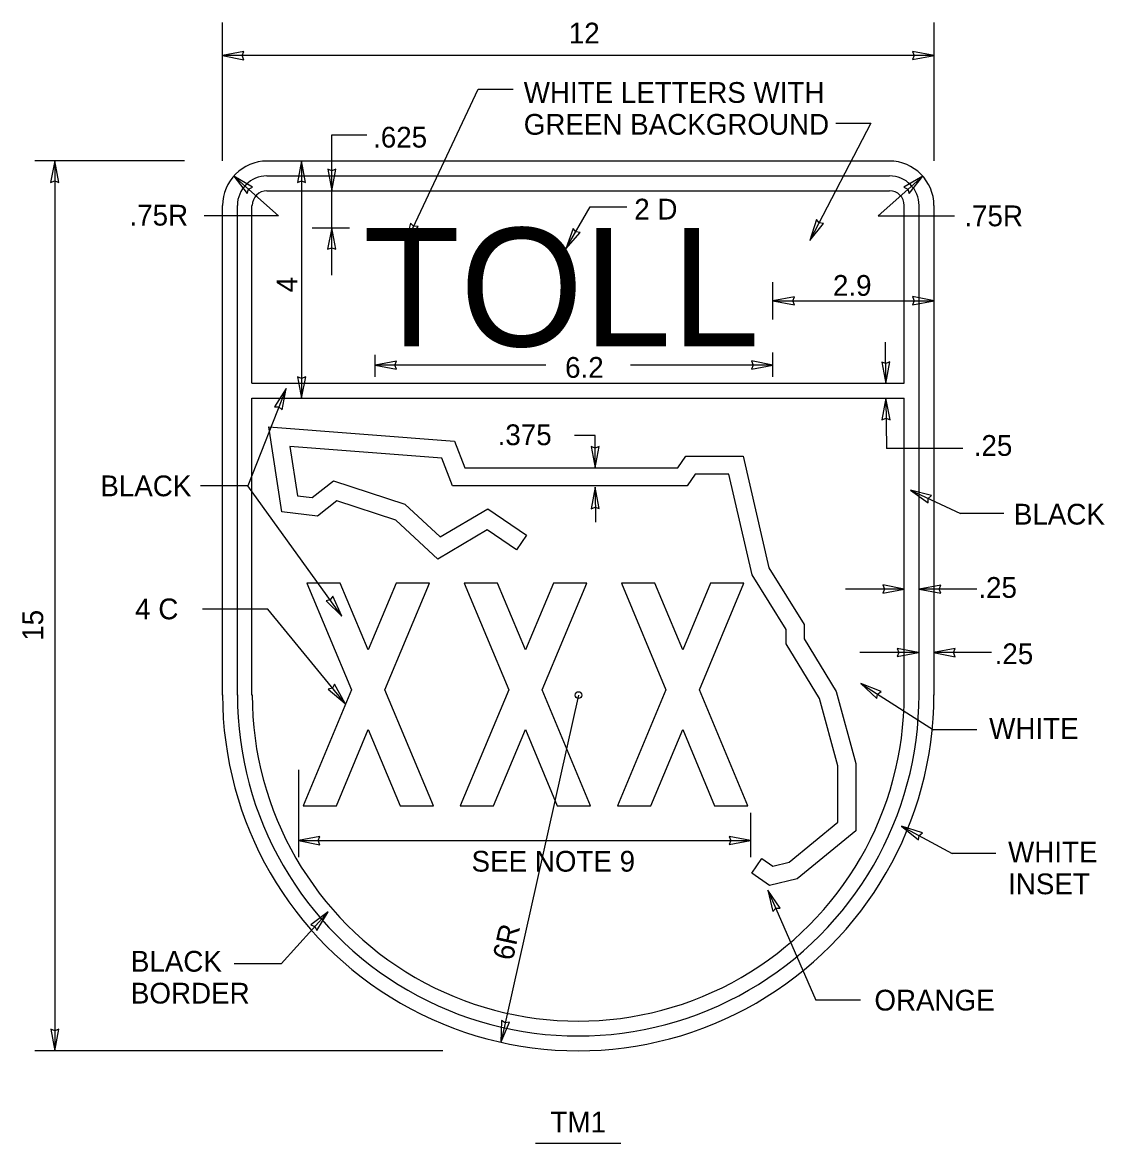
# Model space of a CAD drawing. Extents: x 56108 to 56738, y 11696 to 12112.
# Drawn here: x 56363.6 to 56509.5, y 11960.4 to 12111.6 of the extents above; entities that cross this region are included whole.
import ezdxf

# ---------------------------------------------------------------- set-up
doc = ezdxf.new("R2010")
doc.units = 0
for name, color, linetype in [('GSDims', 7, 'Continuous'), ('SignDetail', 7, 'Continuous'), ('SignPanel', 7, 'Continuous')]:
    doc.layers.add(name, color=color, linetype=linetype)

msp = doc.modelspace()

# ---------------------------------------------------------------- linework, layer by layer
at = {"layer": 'GSDims'}
for p, q in [((56390.53, 12092.88), (56390.53, 12111.55)), ((56486.53, 12092.88), (56486.53, 12111.55)), ((56393.43, 12107.63), (56390.53, 12107.09)), ((56393.21, 12107.09), (56393.43, 12107.63)), ((56486.53, 12107.09), (56483.63, 12107.65)), ((56483.63, 12107.65), (56483.85, 12107.09)), ((56486.53, 12107.09), (56390.53, 12107.09)), ((56390.53, 12107.09), (56393.43, 12106.53)), ((56393.43, 12106.53), (56393.21, 12107.09)), ((56483.85, 12107.09), (56483.63, 12106.55)), ((56483.63, 12106.55), (56486.53, 12107.09)), ((56415.18, 12081.63), (56425.03, 12102.57)), ((56425.03, 12102.57), (56429.76, 12102.57)), ((56478, 12097.95), (56469.79, 12082.15)), ((56473.28, 12097.95), (56478, 12097.95)), ((56405.28, 12088.85), (56405.28, 12096.41)), ((56405.28, 12096.41), (56410.01, 12096.41)), ((56385.42, 12092.88), (56365.24, 12092.88)), ((56367.92, 12092.88), (56367.36, 12089.98)), ((56367.92, 12092.88), (56367.92, 11972.88)), ((56368.46, 12089.98), (56367.92, 12092.88)), ((56401.22, 12092.88), (56400.66, 12089.98)), ((56401.22, 12092.88), (56401.22, 12060.87)), ((56401.76, 12089.98), (56401.22, 12092.88)), ((56486.53, 12092.88), (56486.53, 12092.88)), ((56392.07, 12090.84), (56398.09, 12085.49)), ((56392.07, 12090.84), (56393.86, 12088.5)), ((56394.59, 12089.32), (56392.07, 12090.84)), ((56405.28, 12091.53), (56404.74, 12091.75)), ((56404.74, 12091.75), (56405.28, 12088.85)), ((56405.28, 12088.85), (56405.84, 12091.75)), ((56405.84, 12091.75), (56405.28, 12091.53)), ((56485, 12090.84), (56478.98, 12085.49)), ((56485, 12090.84), (56482.46, 12089.34)), ((56483.19, 12088.51), (56485, 12090.84)), ((56367.36, 12089.98), (56367.92, 12090.2)), ((56367.92, 12090.2), (56368.46, 12089.98)), ((56394.07, 12089.06), (56394.59, 12089.32)), ((56400.66, 12089.98), (56401.22, 12090.2)), ((56401.22, 12090.2), (56401.76, 12089.98)), ((56482.46, 12089.34), (56482.99, 12089.06)), ((56393.86, 12088.5), (56394.07, 12089.06)), ((56405.28, 12083.86), (56405.28, 12088.85)), ((56482.99, 12089.06), (56483.19, 12088.51)), ((56436.85, 12081.01), (56440.14, 12086.67)), ((56440.14, 12086.67), (56445.08, 12086.67)), ((56398.09, 12085.49), (56388.08, 12085.49)), ((56470.65, 12084.97), (56469.79, 12082.15)), ((56471.02, 12084.52), (56470.65, 12084.97)), ((56478.98, 12085.49), (56489.29, 12085.49)), ((56402.65, 12083.86), (56407.66, 12083.86)), ((56405.28, 12083.86), (56404.72, 12080.96)), ((56405.28, 12077.48), (56405.28, 12083.86)), ((56405.82, 12080.96), (56405.28, 12083.86)), ((56415.92, 12084.49), (56415.18, 12081.63)), ((56415.18, 12081.63), (56416.92, 12084.02)), ((56416.32, 12084.06), (56415.92, 12084.49)), ((56416.92, 12084.02), (56416.32, 12084.06)), ((56437.84, 12083.78), (56436.85, 12081.01)), ((56436.85, 12081.01), (56438.79, 12083.23)), ((56438.2, 12083.32), (56437.84, 12083.78)), ((56438.79, 12083.23), (56438.2, 12083.32)), ((56469.79, 12082.15), (56471.62, 12084.46)), ((56471.62, 12084.46), (56471.02, 12084.52)), ((56404.72, 12080.96), (56405.28, 12081.18)), ((56405.28, 12081.18), (56405.82, 12080.96)), ((56464.8, 12071.5), (56464.8, 12076.52)), ((56467.7, 12074.56), (56464.8, 12074.02)), ((56467.48, 12074.02), (56467.7, 12074.56)), ((56486.53, 12074.02), (56483.63, 12074.58)), ((56483.63, 12074.58), (56483.85, 12074.02)), ((56464.8, 12074.02), (56486.53, 12074.02)), ((56464.8, 12074.02), (56467.7, 12073.46)), ((56467.7, 12073.46), (56467.48, 12074.02)), ((56483.85, 12074.02), (56483.63, 12073.48)), ((56483.63, 12073.48), (56486.53, 12074.02)), ((56480.03, 12062.87), (56479.98, 12068.46)), ((56411.12, 12063.75), (56411.12, 12066.73)), ((56464.8, 12063.75), (56464.8, 12067.06)), ((56414.02, 12065.88), (56411.12, 12065.34)), ((56434.17, 12065.34), (56411.12, 12065.34)), ((56411.12, 12065.34), (56414.02, 12064.78)), ((56413.8, 12065.34), (56414.02, 12065.88)), ((56414.02, 12064.78), (56413.8, 12065.34)), ((56464.8, 12065.34), (56445.56, 12065.34)), ((56464.8, 12065.34), (56461.9, 12065.9)), ((56461.9, 12065.9), (56462.12, 12065.34)), ((56462.12, 12065.34), (56461.9, 12064.8)), ((56461.9, 12064.8), (56464.8, 12065.34)), ((56480.01, 12065.55), (56479.47, 12065.76)), ((56479.47, 12065.76), (56480.03, 12062.87)), ((56480.57, 12065.77), (56480.01, 12065.55)), ((56480.03, 12062.87), (56480.57, 12065.77)), ((56401.22, 12063.55), (56400.68, 12063.77)), ((56400.68, 12063.77), (56401.22, 12060.87)), ((56401.22, 12060.87), (56401.78, 12063.77)), ((56401.78, 12063.77), (56401.22, 12063.55)), ((56399.14, 12062.2), (56393.98, 12049.06)), ((56399.14, 12062.2), (56397.56, 12059.7)), ((56398.58, 12059.3), (56399.14, 12062.2)), ((56480.03, 12060.87), (56479.5, 12057.97)), ((56480.03, 12060.87), (56480.1, 12054.11)), ((56480.6, 12057.98), (56480.03, 12060.87)), ((56397.56, 12059.7), (56398.16, 12059.7)), ((56398.16, 12059.7), (56398.58, 12059.3)), ((56479.5, 12057.97), (56480.06, 12058.19)), ((56480.06, 12058.19), (56480.6, 12057.98)), ((56440.8, 12055.87), (56438.04, 12055.87)), ((56440.8, 12054.16), (56440.26, 12054.38)), ((56440.26, 12054.38), (56440.8, 12051.48)), ((56440.8, 12051.48), (56440.8, 12055.87)), ((56440.8, 12051.48), (56441.36, 12054.38)), ((56441.36, 12054.38), (56440.8, 12054.16)), ((56410.03, 12053.44), (56410.03, 12053.44)), ((56490.39, 12054.11), (56480.1, 12054.11)), ((56393.98, 12049.06), (56387.6, 12049.06)), ((56406.65, 12031.51), (56393.98, 12049.06)), ((56440.8, 12048.88), (56440.27, 12045.98)), ((56440.8, 12048.88), (56440.86, 12044.17)), ((56441.37, 12045.99), (56440.8, 12048.88)), ((56483.33, 12048.5), (56490.09, 12045.34)), ((56483.33, 12048.5), (56485.72, 12046.76)), ((56486.18, 12047.76), (56483.33, 12048.5)), ((56485.72, 12046.76), (56485.75, 12047.36)), ((56485.75, 12047.36), (56486.18, 12047.76)), ((56440.27, 12045.98), (56440.83, 12046.2)), ((56440.83, 12046.2), (56441.37, 12045.99)), ((56495.94, 12045.34), (56490.09, 12045.34)), ((56482.5, 12035.15), (56474.59, 12035.15)), ((56482.5, 12035.15), (56479.6, 12035.71)), ((56479.6, 12035.71), (56479.82, 12035.15)), ((56479.82, 12035.15), (56479.6, 12034.61)), ((56479.6, 12034.61), (56482.5, 12035.15)), ((56487.42, 12035.69), (56484.52, 12035.15)), ((56492.31, 12035.15), (56484.52, 12035.15)), ((56484.52, 12035.15), (56487.42, 12034.59)), ((56487.2, 12035.15), (56487.42, 12035.69)), ((56487.42, 12034.59), (56487.2, 12035.15)), ((56405.08, 12033.68), (56404.52, 12033.54)), ((56404.52, 12033.54), (56406.65, 12031.51)), ((56405.41, 12034.19), (56405.08, 12033.68)), ((56406.65, 12031.51), (56405.41, 12034.19)), ((56396.68, 12032.43), (56387.85, 12032.43)), ((56407.08, 12019.73), (56396.68, 12032.43)), ((56484.44, 12026.58), (56476.53, 12026.58)), ((56484.44, 12026.58), (56481.54, 12027.14)), ((56481.54, 12027.14), (56481.76, 12026.58)), ((56481.76, 12026.58), (56481.54, 12026.04)), ((56481.54, 12026.04), (56484.44, 12026.58)), ((56489.36, 12027.12), (56486.46, 12026.58)), ((56494.26, 12026.58), (56486.46, 12026.58)), ((56486.46, 12026.58), (56489.36, 12026.02)), ((56489.14, 12026.58), (56489.36, 12027.12)), ((56489.36, 12026.02), (56489.14, 12026.58)), ((56476.67, 12022.43), (56486.44, 12016.15)), ((56476.67, 12022.43), (56478.8, 12020.39)), ((56479.4, 12021.31), (56476.67, 12022.43)), ((56478.92, 12020.98), (56479.4, 12021.31)), ((56438.56, 12020.85), (56428.1, 11974.01)), ((56478.8, 12020.39), (56478.92, 12020.98)), ((56492.3, 12016.15), (56486.44, 12016.15)), ((56400.79, 12010.76), (56400.79, 11999.01)), ((56461.79, 12004.99), (56461.79, 11999.01)), ((56482.13, 12003.18), (56488.99, 11999.5)), ((56482.13, 12003.18), (56484.43, 12001.31)), ((56484.95, 12002.28), (56482.13, 12003.18)), ((56403.69, 12001.76), (56400.79, 12001.22)), ((56403.47, 12001.22), (56403.69, 12001.76)), ((56461.79, 12001.22), (56458.89, 12001.78)), ((56458.89, 12001.78), (56459.11, 12001.22)), ((56484.43, 12001.31), (56484.5, 12001.91)), ((56484.5, 12001.91), (56484.95, 12002.28)), ((56400.79, 12001.22), (56461.79, 12001.22)), ((56400.79, 12001.22), (56403.69, 12000.66)), ((56403.69, 12000.66), (56403.47, 12001.22)), ((56459.11, 12001.22), (56458.89, 12000.68)), ((56458.89, 12000.68), (56461.79, 12001.22)), ((56494.84, 11999.5), (56488.99, 11999.5)), ((56464.11, 11994.56), (56470.58, 11979.71)), ((56464.11, 11994.56), (56464.76, 11991.68)), ((56465.76, 11992.11), (56464.11, 11994.56)), ((56404.81, 11991.63), (56398.48, 11984.61)), ((56404.81, 11991.63), (56402.46, 11989.85)), ((56403.27, 11989.12), (56404.81, 11991.63)), ((56464.76, 11991.68), (56465.18, 11992.1)), ((56465.18, 11992.1), (56465.76, 11992.11)), ((56402.46, 11989.85), (56403.02, 11989.64)), ((56403.02, 11989.64), (56403.27, 11989.12)), ((56398.48, 11984.61), (56392.11, 11984.61)), ((56476.62, 11979.71), (56470.58, 11979.71)), ((56367.92, 11975.56), (56367.38, 11975.78)), ((56367.38, 11975.78), (56367.92, 11972.88)), ((56367.92, 11972.88), (56368.48, 11975.78)), ((56368.48, 11975.78), (56367.92, 11975.56)), ((56428.2, 11976.96), (56428.1, 11974.01)), ((56428.1, 11974.01), (56429.28, 11976.72)), ((56428.68, 11976.63), (56428.2, 11976.96)), ((56429.28, 11976.72), (56428.68, 11976.63)), ((56420.25, 11972.88), (56365.24, 11972.88)), ((56444.27, 11960.37), (56432.79, 11960.37))]:
    msp.add_line(p, q, dxfattribs=at)
at = {"layer": 'SignDetail'}
for p, q in [((56396.53, 12092.88), (56480.53, 12092.88)), ((56396.53, 12090.87), (56480.53, 12090.87)), ((56396.53, 12088.85), (56480.53, 12088.85)), ((56390.53, 12020.85), (56390.53, 12086.88)), ((56392.55, 12020.85), (56392.55, 12086.88)), ((56394.51, 12062.89), (56394.51, 12086.88)), ((56482.5, 12062.89), (56482.5, 12086.88)), ((56484.52, 12020.85), (56484.52, 12086.88)), ((56486.53, 12020.85), (56486.53, 12086.88)), ((56394.51, 12062.89), (56482.5, 12062.89)), ((56394.51, 12020.85), (56394.51, 12060.87)), ((56394.51, 12060.87), (56482.5, 12060.87)), ((56482.5, 12020.85), (56482.5, 12060.87)), ((56406.43, 12035.93), (56401.94, 12035.93)), ((56401.94, 12035.93), (56407.95, 12021.56)), ((56410.2, 12026.93), (56406.43, 12035.93)), ((56413.97, 12035.93), (56410.2, 12026.93)), ((56412.45, 12021.56), (56418.46, 12035.93)), ((56418.46, 12035.93), (56413.97, 12035.93)), ((56427.64, 12035.93), (56423.15, 12035.93)), ((56423.15, 12035.93), (56429.16, 12021.56)), ((56431.41, 12026.93), (56427.64, 12035.93)), ((56435.18, 12035.93), (56431.41, 12026.93)), ((56433.66, 12021.56), (56439.67, 12035.93)), ((56439.67, 12035.93), (56435.18, 12035.93)), ((56448.85, 12035.93), (56444.36, 12035.93)), ((56444.36, 12035.93), (56450.37, 12021.56)), ((56452.62, 12026.93), (56448.85, 12035.93)), ((56456.39, 12035.93), (56452.62, 12026.93)), ((56454.87, 12021.56), (56460.88, 12035.93)), ((56460.88, 12035.93), (56456.39, 12035.93)), ((56407.95, 12021.56), (56401.41, 12005.93)), ((56405.38, 12021.8), (56404.82, 12021.63)), ((56404.82, 12021.63), (56407.08, 12019.73)), ((56405.67, 12022.33), (56405.38, 12021.8)), ((56407.08, 12019.73), (56405.67, 12022.33)), ((56418.99, 12005.93), (56412.45, 12021.56)), ((56429.16, 12021.56), (56422.62, 12005.93)), ((56440.2, 12005.93), (56433.66, 12021.56)), ((56450.37, 12021.56), (56443.83, 12005.93)), ((56461.41, 12005.93), (56454.87, 12021.56)), ((56405.91, 12005.93), (56410.2, 12016.19)), ((56410.2, 12016.19), (56414.5, 12005.93)), ((56427.11, 12005.93), (56431.41, 12016.19)), ((56431.41, 12016.19), (56435.71, 12005.93)), ((56448.32, 12005.93), (56452.62, 12016.19)), ((56452.62, 12016.19), (56456.92, 12005.93)), ((56401.41, 12005.93), (56405.91, 12005.93)), ((56414.5, 12005.93), (56418.99, 12005.93)), ((56422.62, 12005.93), (56427.11, 12005.93)), ((56435.71, 12005.93), (56440.2, 12005.93)), ((56443.83, 12005.93), (56448.32, 12005.93)), ((56456.92, 12005.93), (56461.41, 12005.93))]:
    msp.add_line(p, q, dxfattribs=at)
for points in [[(56427.11, 12005.93), (56431.41, 12016.19), (56435.71, 12005.93), (56440.2, 12005.93), (56433.66, 12021.56), (56439.67, 12035.93), (56435.18, 12035.93), (56431.41, 12026.93), (56427.64, 12035.93), (56423.15, 12035.93), (56429.16, 12021.56), (56422.62, 12005.93)], [(56448.32, 12005.93), (56452.62, 12016.19), (56456.92, 12005.93), (56461.41, 12005.93), (56454.87, 12021.56), (56460.88, 12035.93), (56456.39, 12035.93), (56452.62, 12026.93), (56448.85, 12035.93), (56444.36, 12035.93), (56450.37, 12021.56), (56443.83, 12005.93)]]:
    msp.add_lwpolyline(points, close=True, dxfattribs=at)
msp.add_circle((56438.56, 12020.85), 0.455, dxfattribs=at)
for centre, major_axis, start_param, end_param in [((56396.55, 12086.86), (0, 6), 0, 1.570796), ((56480.51, 12086.86), (0, 6), 4.712389, 6.283185), ((56396.55, 12086.86), (0, 4), 0, 1.570796), ((56480.51, 12086.86), (0, 4), 4.712389, 6.283185), ((56396.55, 12086.86), (0, 2), 0, 1.570796), ((56480.51, 12086.86), (0, 2), 4.712389, 6.283185), ((56438.53, 12020.87), (0, -47.99), 4.712389, 7.853982), ((56438.53, 12020.87), (0, -45.99), 4.712389, 7.853982), ((56438.53, 12020.87), (0, -43.99), 4.712389, 7.853982)]:
    msp.add_ellipse(centre, major_axis=major_axis, ratio=0.9997, start_param=start_param, end_param=end_param, dxfattribs=at)
at = {"layer": 'SignPanel'}
for p, q in [((56398.56, 12045.55), (56396.78, 12057.01)), ((56396.78, 12057.01), (56421.82, 12055.08)), ((56421.82, 12055.08), (56423.22, 12051.48)), ((56420.12, 12052.79), (56399.63, 12054.37)), ((56399.63, 12054.37), (56400.67, 12047.73)), ((56451.95, 12051.48), (56453.03, 12053.08)), ((56453.03, 12053.08), (56460.76, 12053.08)), ((56460.76, 12053.08), (56464.26, 12038.02)), ((56421.57, 12049.06), (56420.12, 12052.79)), ((56423.22, 12051.48), (56451.95, 12051.48)), ((56454.31, 12050.66), (56453.23, 12049.06)), ((56458.84, 12050.66), (56454.31, 12050.66)), ((56461.99, 12037.08), (56458.84, 12050.66)), ((56402.65, 12047.48), (56405.5, 12049.72)), ((56405.5, 12049.72), (56415.16, 12046.58)), ((56453.23, 12049.06), (56421.57, 12049.06)), ((56400.67, 12047.73), (56402.65, 12047.48)), ((56405.98, 12047.03), (56403.35, 12044.96)), ((56413.91, 12044.45), (56405.98, 12047.03)), ((56403.35, 12044.96), (56398.56, 12045.55)), ((56415.16, 12046.58), (56419.9, 12042.18)), ((56419.9, 12042.18), (56426.33, 12045.96)), ((56426.33, 12045.96), (56431.56, 12042.42)), ((56419.58, 12039.19), (56413.91, 12044.45)), ((56426.24, 12043.11), (56419.58, 12039.19)), ((56430.21, 12040.42), (56426.24, 12043.11)), ((56431.56, 12042.42), (56430.21, 12040.42)), ((56464.26, 12038.02), (56469.02, 12030.37)), ((56466.6, 12029.68), (56461.99, 12037.08)), ((56469.02, 12030.37), (56469.02, 12028.43)), ((56466.6, 12027.76), (56466.6, 12029.68)), ((56471.09, 12020.38), (56466.6, 12027.76)), ((56469.02, 12028.43), (56473.33, 12021.34)), ((56473.33, 12021.34), (56475.98, 12011.63)), ((56473.56, 12011.31), (56471.09, 12020.38)), ((56473.56, 12003.71), (56473.56, 12011.31)), ((56475.98, 12011.63), (56475.98, 12002.56)), ((56466.97, 11998.3), (56473.56, 12003.71)), ((56475.98, 12002.56), (56468.07, 11996.08)), ((56461.93, 11996.83), (56463.31, 11998.82)), ((56463.31, 11998.82), (56464.8, 11997.78)), ((56464.8, 11997.78), (56466.97, 11998.3)), ((56464.31, 11995.18), (56461.93, 11996.83)), ((56468.07, 11996.08), (56464.31, 11995.18))]:
    msp.add_line(p, q, dxfattribs=at)

# ---------------------------------------------------------------- texts
at = {"layer": 'GSDims'}
for s, p in [('12', (56437.26, 12108.72)), ('WHITE LETTERS WITH', (56431.18, 12100.71)), ('GREEN BACKGROUND', (56431.18, 12096.41)), ('.625', (56410.86, 12094.68)), ('2 D', (56446.09, 12084.98)), ('.75R', (56378, 12084.16)), ('.75R', (56490.61, 12084.07)), ('2.9', (56472.89, 12074.69)), ('6.2', (56436.76, 12063.64)), ('.375', (56427.66, 12054.55)), ('.25', (56491.88, 12053.11)), ('BLACK', (56374.07, 12047.66)), ('BLACK', (56497.29, 12043.84)), ('.25', (56492.5, 12033.96)), ('4 C', (56378.77, 12031.07)), ('.25', (56494.7, 12025.02)), ('WHITE', (56493.96, 12014.94)), ('WHITE', (56496.51, 11998.29)), ('SEE NOTE 9', (56424.14, 11997.04)), ('INSET', (56496.51, 11993.99)), ('BLACK', (56378.19, 11983.55)), ('BORDER', (56378.19, 11979.25)), ('ORANGE', (56478.48, 11978.31)), ('TM1', (56434.79, 11961.87))]:
    msp.add_text(s, height=2.8, dxfattribs=at).set_placement(p)
for s, rotation, p in [('4', 90, (56400.66, 12075.15)), ('15', 90, (56366.36, 12028.17)), ('6R', 77.7388, (56429.7, 11984.93))]:
    msp.add_text(s, height=2.8, rotation=rotation, dxfattribs=at).set_placement(p)
at = {"layer": 'SignDetail'}
msp.add_text('TOLL', height=15.981, dxfattribs=at).set_placement((56409.53, 12067.87))

doc.saveas('drawing.dxf')
